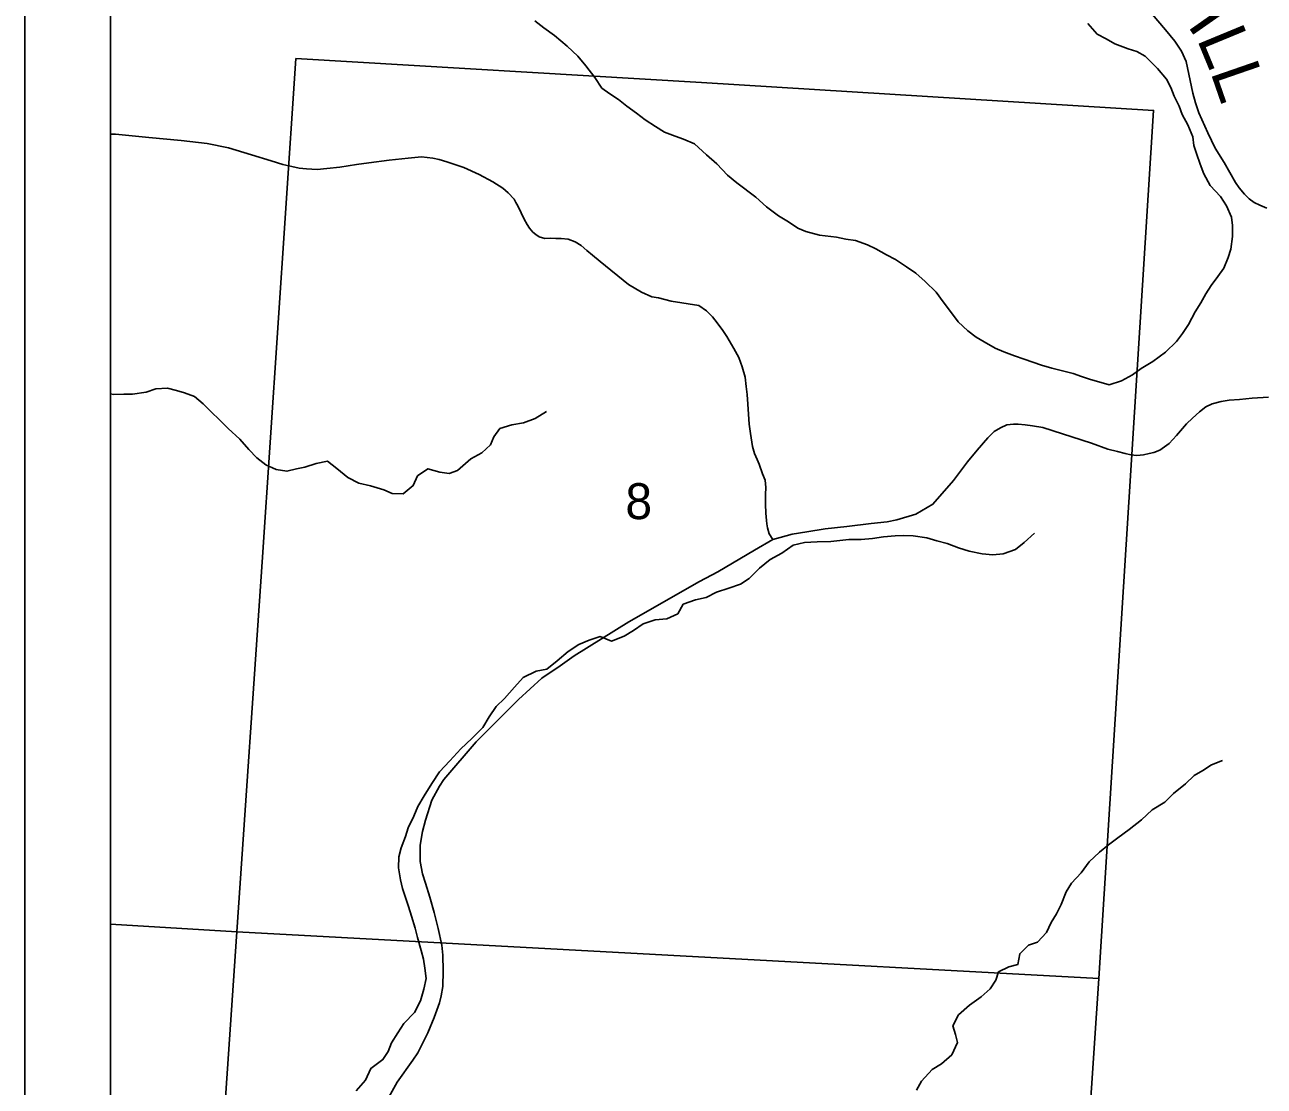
# Model space of a CAD drawing. Extents: x -13.7 to 34, y 0 to 32.3.
# Drawn here: x 23.417 to 24.863, y 15.995 to 17.233 of the extents above; entities that cross this region are included whole.
import ezdxf

# ---------------------------------------------------------------- set-up
doc = ezdxf.new("R2010")
doc.units = 0
for name, color, linetype in [('GM_X_Corporation', 7, 'Continuous'), ('GM_X_County_Road', 7, 'Continuous'), ('GM_X_County_Road_Text', 7, 'Continuous'), ('GM_X_Minor_River', 7, 'Continuous'), ('GM_X_Section_Text', 7, 'Continuous'), ('GM_X_Township_Road', 7, 'Continuous'), ('SH_Data', 7, 'Continuous')]:
    doc.layers.add(name, color=color, linetype=linetype)

msp = doc.modelspace()

# ---------------------------------------------------------------- linework, layer by layer
at = {"layer": 'GM_X_Corporation'}
for points in [[(26.0026, 20.9), (23.5167, 20.9), (23.5167, 14.1)], [(26.0026, 20.9), (23.5167, 20.9), (23.5167, 15.1495)]]:
    msp.add_lwpolyline(points, dxfattribs=at)
for points in [[(23.733, 17.1938), (24.206, 17.166), (24.7334, 17.1333), (24.6695, 16.1208), (23.6639, 16.1752), (23.6938, 16.6123), (23.7207, 17.0133)], [(23.5167, 16.1844), (23.5167, 15.154), (23.5939, 15.1496), (23.6639, 16.1752)], [(23.6639, 16.1752), (24.6695, 16.1208), (24.5999, 15.0816), (23.5939, 15.1496)]]:
    msp.add_lwpolyline(points, close=True, dxfattribs=at)
at = {"layer": 'GM_X_County_Road'}
for points in [[(24.8657, 17.0191), (24.8576, 17.0226), (24.8507, 17.0258), (24.8449, 17.0302), (24.8394, 17.0356), (24.8333, 17.0429), (24.8291, 17.0492), (24.8158, 17.0726), (24.8053, 17.0893), (24.7967, 17.107), (24.7864, 17.1306), (24.7825, 17.142), (24.7793, 17.1535), (24.7716, 17.1902), (24.7662, 17.2024), (24.7584, 17.214), (24.7475, 17.2273), (24.7319, 17.2457)], [(23.8393, 15.9788), (23.8512, 15.9998), (23.8693, 16.0255), (23.8751, 16.0341), (23.8834, 16.0504), (23.8868, 16.0575), (23.8943, 16.0752), (23.9004, 16.0925), (23.9024, 16.1007), (23.9042, 16.1115), (23.9049, 16.1298), (23.9042, 16.1479), (23.9031, 16.1596), (23.899, 16.179), (23.8941, 16.198), (23.8892, 16.2159), (23.884, 16.2321), (23.8807, 16.243), (23.8778, 16.2573), (23.8778, 16.2763), (23.8807, 16.2922), (23.884, 16.3057), (23.8916, 16.3289), (23.9004, 16.3453), (23.9055, 16.3529), (23.9434, 16.3967), (23.9928, 16.4461), (24.0198, 16.4712), (24.0411, 16.4857), (24.0577, 16.4971), (24.1212, 16.5367), (24.2037, 16.5837), (24.2251, 16.5953), (24.2679, 16.6204), (24.2894, 16.6329), (24.2978, 16.6352), (24.3119, 16.6391), (24.329, 16.6419), (24.3504, 16.6452), (24.3758, 16.6482), (24.4042, 16.6515), (24.4228, 16.6536), (24.4341, 16.6556), (24.4562, 16.6623), (24.4761, 16.674), (24.5, 16.7017), (24.5165, 16.7234), (24.5275, 16.7371), (24.5401, 16.7516), (24.5477, 16.7587), (24.5548, 16.7629), (24.5624, 16.7665), (24.57, 16.7672), (24.5756, 16.7672), (24.5837, 16.7666), (24.5923, 16.7653), (24.6043, 16.7633), (24.6611, 16.7453), (24.6801, 16.7384), (24.6912, 16.7354), (24.7003, 16.733), (24.707, 16.7315), (24.7139, 16.731), (24.7217, 16.7317), (24.7283, 16.733), (24.7337, 16.7345), (24.7408, 16.7371), (24.7516, 16.7447), (24.7603, 16.7542), (24.7718, 16.7677), (24.779, 16.7742), (24.7872, 16.7817), (24.7946, 16.7874), (24.802, 16.7911), (24.8124, 16.7939), (24.8215, 16.7952), (24.8338, 16.7962), (24.8485, 16.7975), (24.8676, 16.799)]]:
    msp.add_lwpolyline(points, dxfattribs=at)
at = {"layer": 'GM_X_Minor_River'}
for points in [[(24.0117, 17.2378), (24.0223, 17.2295), (24.0348, 17.2208), (24.0492, 17.2083), (24.0617, 17.1965), (24.0712, 17.1852), (24.0818, 17.1715), (24.0898, 17.1594), (24.0993, 17.1526), (24.1091, 17.1462), (24.119, 17.1382), (24.1304, 17.1299), (24.1402, 17.1223), (24.1524, 17.1144), (24.163, 17.1079), (24.1755, 17.1034), (24.185, 17.0996), (24.1978, 17.0943), (24.2119, 17.0814), (24.224, 17.0708), (24.2365, 17.0576), (24.2475, 17.0489), (24.2695, 17.0322), (24.282, 17.0209), (24.296, 17.0103), (24.3074, 17.0035), (24.3184, 16.9959), (24.3279, 16.9921), (24.3438, 16.9876), (24.3635, 16.9853), (24.3745, 16.9831), (24.3859, 16.9816), (24.3999, 16.9767), (24.4094, 16.9717), (24.4219, 16.9649), (24.4325, 16.9593), (24.4454, 16.9509), (24.456, 16.9434), (24.467, 16.9339), (24.4799, 16.9214), (24.4882, 16.91), (24.4954, 16.9002), (24.5057, 16.8869), (24.5167, 16.8763), (24.5265, 16.8687), (24.536, 16.8634), (24.5485, 16.8559), (24.5588, 16.8517), (24.5713, 16.8472), (24.5826, 16.843), (24.5925, 16.8396), (24.6027, 16.8362), (24.6148, 16.8328), (24.6273, 16.8294), (24.6395, 16.8264), (24.6493, 16.823), (24.6599, 16.8193), (24.6698, 16.8166), (24.6815, 16.8132), (24.6959, 16.8178), (24.7088, 16.825), (24.719, 16.8322), (24.7326, 16.8406), (24.7474, 16.8512), (24.7603, 16.8638)], [(24.7603, 16.8638), (24.7671, 16.8732), (24.7742, 16.8835), (24.7818, 16.8983), (24.7886, 16.9089), (24.7943, 16.9192), (24.8007, 16.929), (24.8083, 16.9397), (24.8155, 16.9492), (24.8204, 16.9617), (24.8234, 16.9715), (24.8256, 16.9863), (24.8256, 16.9989), (24.8245, 17.0087), (24.8184, 17.022), (24.8116, 17.033), (24.7994, 17.0458), (24.7922, 17.0595), (24.788, 17.0705), (24.7835, 17.083), (24.7804, 17.0925), (24.7793, 17.1023), (24.7736, 17.1163), (24.7667, 17.1285), (24.7633, 17.1383), (24.7576, 17.1501), (24.7535, 17.1599), (24.7485, 17.1698), (24.7379, 17.1823), (24.7235, 17.1967), (24.714, 17.202), (24.7038, 17.205), (24.6882, 17.211), (24.678, 17.2167), (24.6678, 17.2224), (24.6568, 17.2345)], [(23.5167, 16.8027), (23.5201, 16.8021), (23.5323, 16.8025), (23.5425, 16.8022), (23.5584, 16.8048), (23.5694, 16.8086), (23.583, 16.8094), (23.5936, 16.8068), (23.6031, 16.8041), (23.6145, 16.7996), (23.6247, 16.7909), (23.6342, 16.7818), (23.6437, 16.7723), (23.6539, 16.7625), (23.6676, 16.75), (23.6782, 16.7379), (23.6873, 16.728), (23.6979, 16.7201), (23.71, 16.7144), (23.7225, 16.7125), (23.7335, 16.7152), (23.7434, 16.7171), (23.7566, 16.7213), (23.7699, 16.7244), (23.7805, 16.7156), (23.7934, 16.705), (23.8063, 16.6986), (23.8199, 16.6956), (23.8354, 16.6907), (23.8453, 16.6865), (23.8582, 16.6862), (23.8699, 16.6957), (23.8748, 16.7071), (23.8869, 16.7154), (23.901, 16.7113), (23.9116, 16.7098), (23.9214, 16.7132), (23.9369, 16.7269), (23.9498, 16.7341), (23.96, 16.7432), (23.9638, 16.7527), (23.971, 16.7622), (23.985, 16.7664), (23.9986, 16.769), (24.0119, 16.774), (24.0251, 16.782)], [(23.8034, 15.9898), (23.8143, 16.0023), (23.8204, 16.016), (23.8344, 16.0263), (23.8404, 16.0358), (23.8446, 16.046), (23.8518, 16.0574), (23.8589, 16.0684), (23.8711, 16.0813), (23.8782, 16.095), (23.882, 16.1083), (23.885, 16.1208), (23.8835, 16.1329), (23.8816, 16.1435), (23.8789, 16.1534), (23.8747, 16.1685), (23.8721, 16.1795), (23.8679, 16.1936), (23.8641, 16.2049), (23.8607, 16.2155), (23.8572, 16.2258), (23.8549, 16.236), (23.8527, 16.25), (23.853, 16.2629), (23.8557, 16.2732), (23.8606, 16.2865), (23.864, 16.2967), (23.8704, 16.31), (23.8753, 16.3214), (23.8825, 16.3339), (23.8916, 16.3483), (23.9006, 16.362), (23.9124, 16.3749), (23.9252, 16.3889), (23.9381, 16.4007), (23.9509, 16.4136), (23.9585, 16.4262), (23.9664, 16.4379), (23.9763, 16.4474), (23.988, 16.4607), (23.9982, 16.4721), (24.0134, 16.4793), (24.0255, 16.4816), (24.0376, 16.4915), (24.0505, 16.5021), (24.0629, 16.5105), (24.0751, 16.5154), (24.0879, 16.5196), (24.1012, 16.5143), (24.116, 16.52), (24.1266, 16.5269), (24.1379, 16.5345), (24.1519, 16.5391), (24.1656, 16.5402), (24.1784, 16.5463), (24.1849, 16.5573), (24.1989, 16.5626), (24.2114, 16.5653), (24.2235, 16.5714), (24.2379, 16.576), (24.2515, 16.5809), (24.2617, 16.5874), (24.2738, 16.5995), (24.2863, 16.6094), (24.2999, 16.617), (24.3132, 16.6261), (24.3261, 16.6292), (24.3412, 16.63), (24.3571, 16.6307), (24.3674, 16.6315), (24.378, 16.6327), (24.3924, 16.6327), (24.4056, 16.6342), (24.4185, 16.6361), (24.4321, 16.6373), (24.442, 16.6377), (24.453, 16.6373), (24.4689, 16.6347), (24.4806, 16.6313), (24.4927, 16.6283), (24.506, 16.623), (24.5185, 16.6192), (24.5337, 16.6162), (24.5458, 16.6151), (24.5579, 16.6162), (24.5723, 16.6212), (24.5825, 16.6295), (24.5946, 16.6402)], [(24.4568, 15.9907), (24.4628, 16.001), (24.4753, 16.0146), (24.4859, 16.0215), (24.498, 16.0317), (24.5048, 16.0462), (24.5025, 16.0556), (24.4991, 16.0655), (24.5059, 16.0784), (24.5188, 16.0898), (24.5324, 16.0993), (24.543, 16.1088), (24.5494, 16.119), (24.5525, 16.1285), (24.5646, 16.1346), (24.5752, 16.1373), (24.5774, 16.1498), (24.5876, 16.1597), (24.5979, 16.1631), (24.6085, 16.1745), (24.6141, 16.1862), (24.6202, 16.1961), (24.6255, 16.2071), (24.6315, 16.2219), (24.6376, 16.2322), (24.6489, 16.2439), (24.6584, 16.2568), (24.6705, 16.2682), (24.6807, 16.2766), (24.6917, 16.285), (24.7049, 16.2945), (24.7193, 16.3058), (24.7318, 16.3176), (24.7465, 16.3264), (24.7567, 16.3366), (24.7707, 16.348), (24.781, 16.3575), (24.7908, 16.3636), (24.801, 16.3701), (24.8139, 16.375)]]:
    msp.add_lwpolyline(points, dxfattribs=at)
at = {"layer": 'GM_X_Township_Road'}
msp.add_lwpolyline([(23.5167, 17.1056), (23.5225, 17.1054), (23.5614, 17.1018), (23.599, 17.0981), (23.6295, 17.0947), (23.6543, 17.0896), (23.6811, 17.0813), (23.704, 17.0743), (23.7176, 17.0703), (23.7283, 17.0678), (23.7369, 17.0661), (23.7454, 17.065), (23.7576, 17.0645), (23.769, 17.0654), (23.784, 17.067), (23.8038, 17.0701), (23.8181, 17.0721), (23.8416, 17.0752), (23.8639, 17.0777), (23.8796, 17.079), (23.8928, 17.0775), (23.9002, 17.0761), (23.9091, 17.0734), (23.9288, 17.0669), (23.9469, 17.0587), (23.9626, 17.0499), (23.9742, 17.0426), (23.9805, 17.037), (23.9874, 17.0298), (23.9896, 17.026), (23.9917, 17.022), (23.9959, 17.0137), (23.9993, 17.0066), (24.0028, 17.0001), (24.0053, 16.996), (24.0093, 16.9913), (24.0129, 16.9884), (24.0167, 16.9857), (24.0232, 16.984), (24.0299, 16.9842), (24.0362, 16.9838), (24.0425, 16.984), (24.0505, 16.9833), (24.0586, 16.9802), (24.0657, 16.9757), (24.0722, 16.9699), (24.0789, 16.9643), (24.0879, 16.9569), (24.1208, 16.9301), (24.1362, 16.9213), (24.148, 16.9157), (24.1561, 16.9146), (24.1706, 16.911), (24.2031, 16.9057), (24.2118, 16.8996), (24.2189, 16.8925), (24.2243, 16.8857), (24.231, 16.8768), (24.2357, 16.8696), (24.244, 16.8558), (24.2496, 16.845), (24.2537, 16.8343), (24.2572, 16.822), (24.2583, 16.8112), (24.2594, 16.8021), (24.2601, 16.7905), (24.2617, 16.7674), (24.2632, 16.7564), (24.2657, 16.7415), (24.2679, 16.733), (24.2709, 16.7262), (24.2735, 16.7209), (24.2774, 16.7094), (24.2805, 16.7019), (24.2811, 16.6936), (24.2809, 16.6855), (24.2809, 16.6741), (24.2812, 16.6634), (24.282, 16.6549), (24.2823, 16.6511), (24.283, 16.6466), (24.2852, 16.6394), (24.2894, 16.6329)], dxfattribs=at)
at = {"layer": 'SH_Data'}
for points in [[(23.4167, 21), (30.4167, 21), (30.4167, 14), (23.4167, 14)], [(23.5167, 20.9), (30.3167, 20.9), (30.3167, 14.1), (23.5167, 14.1)]]:
    msp.add_lwpolyline(points, close=True, dxfattribs=at)

# ---------------------------------------------------------------- texts
at = {"layer": 'GM_X_County_Road_Text'}
for s, rotation, p in [('I', 305.0195, (24.7717, 17.2332)), ('L', 292.4524, (24.7835, 17.2169)), ('L', 289.0692, (24.7994, 17.1785))]:
    msp.add_text(s, height=0.0568, rotation=rotation, dxfattribs=at).set_placement(p)
at = {"layer": 'GM_X_Section_Text'}
msp.add_text('8', height=0.0419, rotation=0, dxfattribs=at).set_placement((24.1173, 16.6566))

doc.saveas('drawing.dxf')
